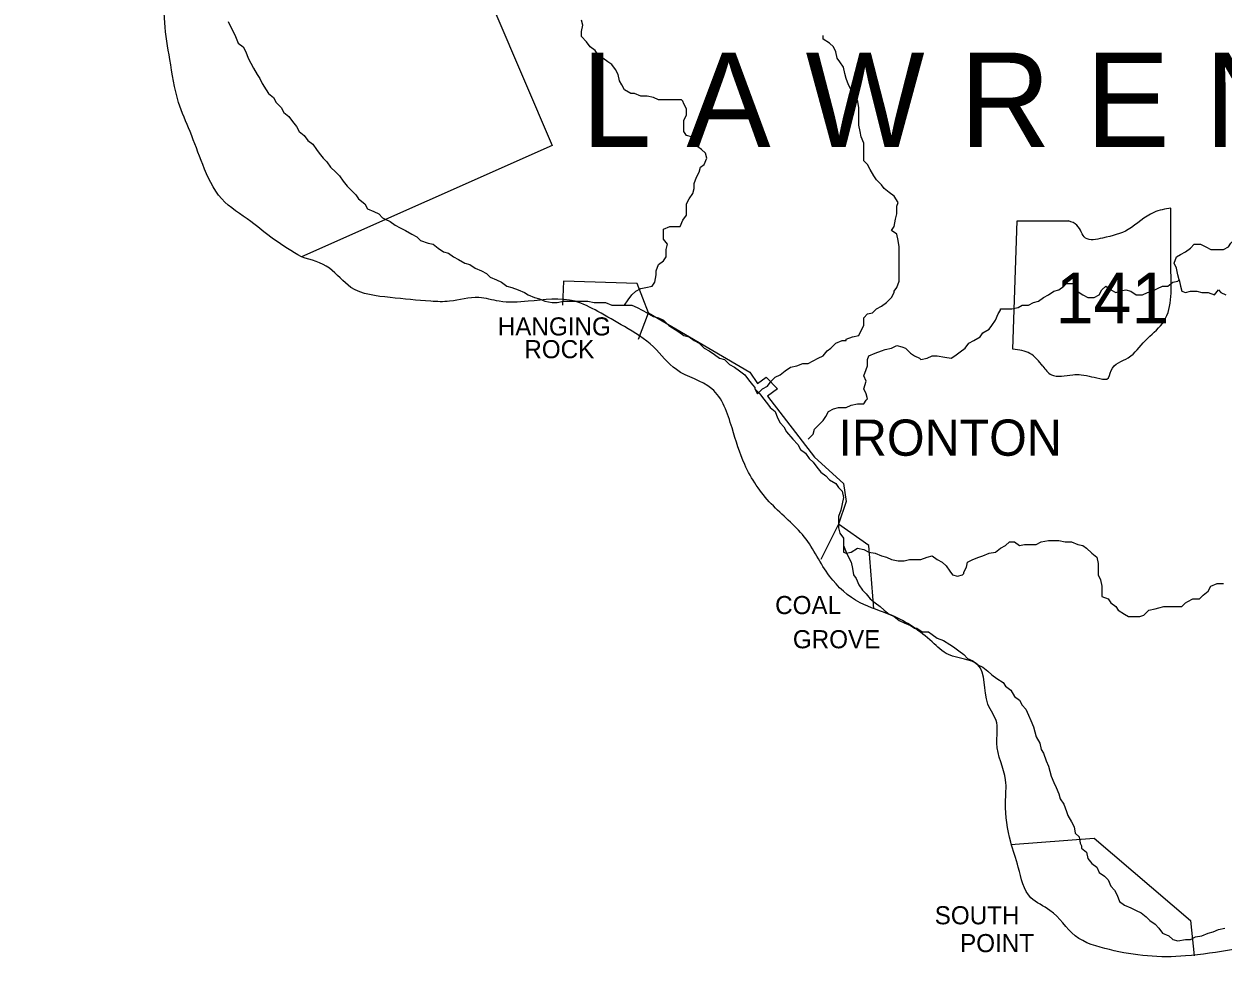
# Model space of a CAD drawing. Extents: x 0 to 40.2, y 0 to 22.
# Drawn here: x 6.366 to 7.657, y 14.906 to 15.911 of the extents above; entities that cross this region are included whole.
import ezdxf

# ---------------------------------------------------------------- set-up
doc = ezdxf.new("R2010")
doc.units = 0
doc.layers.add('Default', color=7, linetype='Continuous')
doc.layers.add('TR_Turning_Path1', color=7, linetype='Continuous')

msp = doc.modelspace()

# ---------------------------------------------------------------- linework, layer by layer
at = {"layer": 'Default'}
for points in [[(6.8528, 16.1563), (6.8419, 15.9968), (6.9346, 15.78), (6.6647, 15.66)], [(6.5856, 15.9136), (6.5883, 15.9082), (6.5911, 15.9027), (6.5938, 15.8973), (6.5965, 15.8904), (6.602, 15.8864), (6.6047, 15.8809), (6.6074, 15.8741), (6.6101, 15.8686), (6.6129, 15.8632), (6.617, 15.8564), (6.6197, 15.8523), (6.6224, 15.8468), (6.6265, 15.84), (6.6292, 15.8359), (6.6347, 15.8318), (6.6374, 15.8264), (6.6429, 15.8209), (6.6456, 15.8155), (6.6511, 15.8114), (6.6551, 15.8059), (6.6592, 15.8005), (6.662, 15.795), (6.6674, 15.7909), (6.6715, 15.7855), (6.677, 15.7814), (6.681, 15.7759), (6.6838, 15.7718), (6.6879, 15.7664), (6.692, 15.7623), (6.696, 15.7568), (6.7015, 15.7514), (6.7056, 15.7473), (6.7097, 15.7418), (6.7138, 15.7364), (6.7179, 15.7323), (6.7233, 15.7268), (6.726, 15.7227), (6.7329, 15.7173), (6.7356, 15.7118), (6.7424, 15.7091), (6.7479, 15.7064), (6.7519, 15.7023), (6.7547, 15.7009)], [(7.0737, 15.8291), (7.0683, 15.8291), (7.0614, 15.8291), (7.0546, 15.8291), (7.0492, 15.8291), (7.0437, 15.8318), (7.0369, 15.8332), (7.0301, 15.8332), (7.0233, 15.8359), (7.0192, 15.8359), (7.0124, 15.84), (7.0096, 15.8454), (7.0069, 15.8495), (7.0055, 15.8564), (7.0028, 15.8618), (6.9987, 15.8673), (6.9946, 15.87), (6.9892, 15.8741), (6.9837, 15.8782), (6.981, 15.8823), (6.9755, 15.8864), (6.9715, 15.8918), (6.966, 15.8973), (6.966, 15.9027), (6.9674, 15.9095), (6.966, 15.915)], [(7.2619, 15.8291), (7.2605, 15.8359), (7.2564, 15.84), (7.2537, 15.8454), (7.251, 15.8523), (7.2496, 15.8577), (7.2482, 15.8645), (7.2441, 15.87), (7.2414, 15.8741), (7.2401, 15.8809), (7.2373, 15.8864), (7.2332, 15.8904), (7.2264, 15.8945), (7.2264, 15.8986)], [(7.0983, 15.7596), (7.101, 15.7664), (7.0996, 15.7718), (7.0955, 15.7759), (7.0914, 15.7786), (7.0873, 15.7827), (7.0846, 15.7895), (7.0792, 15.7909), (7.0764, 15.795), (7.0764, 15.8005), (7.0764, 15.8073), (7.0792, 15.8127), (7.0792, 15.8195), (7.0764, 15.825), (7.0751, 15.8277), (7.0737, 15.8291)], [(7.3069, 15.6777), (7.3055, 15.6846), (7.3, 15.6887), (7.3028, 15.6927), (7.3041, 15.7009), (7.3055, 15.7064), (7.3055, 15.7146), (7.3069, 15.7187), (7.3028, 15.7255), (7.2973, 15.7296), (7.2919, 15.7336), (7.2891, 15.7377), (7.2837, 15.7432), (7.281, 15.7473), (7.2769, 15.7541), (7.2741, 15.7596), (7.27, 15.7636), (7.27, 15.7705), (7.27, 15.7773), (7.27, 15.7827), (7.2673, 15.7895), (7.266, 15.795), (7.2646, 15.8018), (7.2646, 15.8086), (7.2646, 15.8155), (7.2646, 15.8209), (7.2632, 15.8291), (7.2619, 15.8291)], [(7.0574, 15.6614), (7.0574, 15.6682), (7.0587, 15.6737), (7.0546, 15.6791), (7.0546, 15.6846), (7.0546, 15.69), (7.0614, 15.6927), (7.0683, 15.6927), (7.0723, 15.6927), (7.0751, 15.6996), (7.0792, 15.705), (7.0792, 15.7105), (7.0792, 15.7173), (7.0819, 15.7227), (7.086, 15.7282), (7.0873, 15.7336), (7.0873, 15.7391), (7.0901, 15.7459), (7.0928, 15.7514), (7.0942, 15.7568), (7.0983, 15.7596), (7.0983, 15.7596)], [(7.6008, 15.6436), (7.6008, 15.7126)], [(6.7547, 15.7009), (6.7601, 15.6982), (6.7656, 15.6941), (6.771, 15.6914), (6.7765, 15.6887), (6.7833, 15.6846), (6.7888, 15.6818), (6.7928, 15.6777), (6.801, 15.675), (6.8065, 15.6737), (6.8119, 15.6696), (6.8174, 15.6655), (6.8228, 15.6641), (6.8283, 15.66), (6.8338, 15.6573), (6.8406, 15.6532), (6.846, 15.6518), (6.8515, 15.6478), (6.8583, 15.645), (6.8637, 15.6423), (6.8678, 15.6382), (6.8747, 15.6355), (6.8801, 15.6328), (6.8856, 15.6287), (6.891, 15.6273), (6.8978, 15.6246), (6.9046, 15.6218), (6.9087, 15.6191), (6.9156, 15.6164), (6.921, 15.615), (6.9265, 15.6123), (6.9346, 15.6109), (6.9401, 15.6109), (6.9469, 15.6123), (6.9537, 15.6123), (6.9592, 15.6123), (6.966, 15.6123), (6.9728, 15.6123), (6.9796, 15.6109), (6.9865, 15.6109), (6.9919, 15.6109), (6.9987, 15.6082), (7.0055, 15.6082), (7.0069, 15.6082)], [(7.4306, 15.5608), (7.4352, 15.6988), (7.4904, 15.6988)], [(7.6095, 15.6355), (7.6082, 15.6409), (7.6068, 15.6478), (7.6041, 15.6532), (7.6068, 15.66), (7.6109, 15.6628), (7.6164, 15.6655), (7.6218, 15.6696), (7.6259, 15.6737), (7.6327, 15.6737), (7.6382, 15.6709), (7.6436, 15.6682), (7.6504, 15.6682), (7.6573, 15.6682), (7.6627, 15.6709), (7.6654, 15.675), (7.6709, 15.6805), (7.675, 15.6846), (7.6818, 15.6887), (7.6818, 15.6887), (7.6832, 15.69)], [(7.3028, 15.6232), (7.3055, 15.6273), (7.3082, 15.6341), (7.3082, 15.6409), (7.3082, 15.6464), (7.3082, 15.6518), (7.3082, 15.66), (7.3082, 15.6655), (7.3082, 15.6709), (7.3069, 15.6777), (7.3069, 15.6777)], [(7.3028, 15.6232), (7.3055, 15.6273), (7.3082, 15.6341), (7.3082, 15.6409), (7.3082, 15.6464), (7.3082, 15.6518), (7.3082, 15.66), (7.3082, 15.6655), (7.3082, 15.6709), (7.3069, 15.6777), (7.3069, 15.6777)], [(7.0069, 15.6082), (7.0124, 15.6082), (7.0164, 15.6137), (7.0205, 15.6191), (7.0246, 15.6232), (7.0301, 15.6259), (7.0355, 15.6273), (7.0424, 15.6287), (7.0451, 15.6328), (7.0464, 15.6409), (7.0464, 15.645), (7.0492, 15.6518), (7.0546, 15.6559), (7.0574, 15.66), (7.0574, 15.6614)], [(7.0274, 15.5714), (7.0383, 15.6), (7.026, 15.6314), (6.9469, 15.6341), (6.9456, 15.6082)], [(7.5114, 15.6164), (7.5182, 15.6164), (7.5236, 15.6191), (7.5264, 15.6246), (7.5305, 15.6287), (7.5359, 15.6246), (7.5414, 15.6218), (7.5455, 15.6232), (7.5523, 15.6246), (7.5577, 15.6232), (7.5632, 15.6191), (7.57, 15.6191), (7.5755, 15.6218), (7.5809, 15.6232), (7.5864, 15.6259), (7.5918, 15.6287), (7.5973, 15.6287), (7.6027, 15.6328), (7.6082, 15.6341), (7.6095, 15.6355)], [(7.6095, 15.6355), (7.6109, 15.6287), (7.6123, 15.6232), (7.6164, 15.6218), (7.6218, 15.6232), (7.6286, 15.6232), (7.6341, 15.6218), (7.6409, 15.6218), (7.6477, 15.6191), (7.6518, 15.6246), (7.6545, 15.6218), (7.66, 15.6191)], [(7.251, 15.5714), (7.2578, 15.5741), (7.2646, 15.5755), (7.2673, 15.5809), (7.27, 15.5864), (7.27, 15.5946), (7.2741, 15.5987), (7.2796, 15.6), (7.2837, 15.6041), (7.2891, 15.6069), (7.2946, 15.6109), (7.3, 15.6164), (7.3028, 15.6218), (7.3028, 15.6232)], [(7.251, 15.5714), (7.2578, 15.5741), (7.2646, 15.5755), (7.2673, 15.5809), (7.27, 15.5864), (7.27, 15.5946), (7.2741, 15.5987), (7.2796, 15.6), (7.2837, 15.6041), (7.2891, 15.6069), (7.2946, 15.6109), (7.3, 15.6164), (7.3028, 15.6218), (7.3028, 15.6232)], [(7.4173, 15.6041), (7.4227, 15.6041), (7.4296, 15.6041), (7.4364, 15.6055), (7.4405, 15.6082), (7.4473, 15.6082), (7.4527, 15.6109), (7.4582, 15.6123), (7.4637, 15.6164), (7.4691, 15.6191), (7.4746, 15.6232), (7.48, 15.6246), (7.4855, 15.6287), (7.4882, 15.6314), (7.495, 15.6314), (7.4964, 15.6259), (7.5018, 15.6218), (7.5059, 15.6191), (7.5114, 15.6164), (7.5114, 15.6164), (7.5114, 15.6164)], [(7.0069, 15.6082), (7.0137, 15.6082), (7.0205, 15.6082), (7.026, 15.6055), (7.0314, 15.6028), (7.0369, 15.6), (7.0437, 15.5959), (7.0492, 15.5946), (7.0546, 15.5919), (7.0601, 15.5864), (7.0642, 15.5837), (7.071, 15.5796), (7.0764, 15.5755), (7.0819, 15.5741), (7.0873, 15.57), (7.0928, 15.5673), (7.0983, 15.5619), (7.1037, 15.5591), (7.1092, 15.555), (7.1146, 15.551), (7.1201, 15.5496), (7.1255, 15.5441), (7.131, 15.5414), (7.1364, 15.5373), (7.1419, 15.5332), (7.146, 15.5278), (7.1501, 15.5223), (7.1528, 15.5196), (7.1528, 15.5196), (7.1528, 15.5182)], [(7.0383, 15.6), (7.1473, 15.536), (7.1555, 15.5237), (7.1651, 15.5305), (7.1773, 15.5182), (7.1664, 15.51), (7.2169, 15.4446), (7.2482, 15.416), (7.251, 15.3969), (7.2428, 15.3723)], [(7.3314, 15.5496), (7.3382, 15.551), (7.3437, 15.5537), (7.3491, 15.5537), (7.3573, 15.5523), (7.3641, 15.551), (7.3682, 15.5537), (7.3737, 15.5578), (7.3791, 15.5619), (7.3832, 15.5673), (7.3887, 15.57), (7.3955, 15.5741), (7.3982, 15.5782), (7.405, 15.5823), (7.4078, 15.5864), (7.4118, 15.5919), (7.4146, 15.5987), (7.4173, 15.6028), (7.4173, 15.6041)], [(7.1528, 15.5182), (7.1555, 15.5128), (7.161, 15.5182), (7.1664, 15.521), (7.1705, 15.5264), (7.1746, 15.5305), (7.1801, 15.5332), (7.1855, 15.5373), (7.191, 15.5414), (7.1978, 15.5428), (7.2046, 15.5455), (7.2101, 15.5455), (7.2155, 15.5482), (7.221, 15.551), (7.2264, 15.5537), (7.2305, 15.5591), (7.2346, 15.5619), (7.2401, 15.5673), (7.2469, 15.57), (7.251, 15.57), (7.251, 15.5714)], [(7.1528, 15.5182), (7.1555, 15.5128), (7.161, 15.5182), (7.1664, 15.521), (7.1705, 15.5264), (7.1746, 15.5305), (7.1801, 15.5332), (7.1855, 15.5373), (7.191, 15.5414), (7.1978, 15.5428), (7.2046, 15.5455), (7.2101, 15.5455), (7.2155, 15.5482), (7.221, 15.551), (7.2264, 15.5537), (7.2305, 15.5591), (7.2346, 15.5619), (7.2401, 15.5673), (7.2469, 15.57), (7.251, 15.57), (7.251, 15.5714)], [(7.2741, 15.5073), (7.2728, 15.5128), (7.27, 15.5182), (7.2728, 15.5264), (7.27, 15.5319), (7.2728, 15.5387), (7.2741, 15.5428), (7.2741, 15.5496), (7.2755, 15.5537), (7.2823, 15.5564), (7.2891, 15.5591), (7.2932, 15.5605), (7.3, 15.5619), (7.3055, 15.5646), (7.3109, 15.5632), (7.315, 15.5619), (7.3205, 15.5564), (7.3246, 15.5537), (7.33, 15.551), (7.3314, 15.5496), (7.3314, 15.5496)], [(7.1528, 15.5182), (7.1582, 15.5128), (7.161, 15.5087), (7.1664, 15.5019), (7.1692, 15.4978), (7.1746, 15.4937), (7.1773, 15.4869), (7.1801, 15.4814), (7.1841, 15.4773), (7.1869, 15.4719), (7.1937, 15.4637), (7.1937, 15.4637)], [(7.2101, 15.4637), (7.2155, 15.4691), (7.2169, 15.4746), (7.221, 15.4787), (7.2264, 15.4841), (7.2291, 15.4882), (7.2319, 15.4937), (7.2373, 15.4964), (7.2428, 15.4978), (7.251, 15.4978), (7.2564, 15.5005), (7.2632, 15.5019), (7.27, 15.5019), (7.2728, 15.506), (7.2741, 15.5073)], [(7.1937, 15.4637), (7.1991, 15.4582), (7.2019, 15.4528), (7.2073, 15.4487), (7.2114, 15.4432), (7.2155, 15.4391), (7.2196, 15.4337), (7.2237, 15.4282), (7.2291, 15.4242), (7.2332, 15.4201), (7.2401, 15.416), (7.2428, 15.4119), (7.2469, 15.4078), (7.2482, 15.401), (7.2469, 15.3942), (7.2455, 15.3873), (7.2428, 15.3805), (7.2428, 15.3751), (7.2428, 15.3683), (7.2441, 15.3628), (7.2482, 15.3573), (7.2482, 15.3492), (7.2482, 15.3492)], [(7.281, 15.281), (7.2755, 15.3492), (7.2428, 15.3723), (7.2237, 15.3342)], [(7.2482, 15.3492), (7.251, 15.3423), (7.2537, 15.3369), (7.2564, 15.3314), (7.2578, 15.3246), (7.2591, 15.3178), (7.2619, 15.3137), (7.2646, 15.3069), (7.2687, 15.3014), (7.2728, 15.2974), (7.2769, 15.2919), (7.2823, 15.2878), (7.2878, 15.2837), (7.2919, 15.2796), (7.2973, 15.2755), (7.3028, 15.2728), (7.3082, 15.2687), (7.3137, 15.266), (7.3205, 15.2633), (7.3246, 15.2605), (7.3273, 15.2605)], [(7.2482, 15.3492), (7.2482, 15.3423), (7.251, 15.341), (7.2564, 15.3423), (7.2632, 15.3464), (7.27, 15.3451), (7.2755, 15.3423), (7.2823, 15.341), (7.2891, 15.3383), (7.2946, 15.3369), (7.3, 15.3342), (7.3069, 15.3328), (7.3137, 15.3328), (7.3191, 15.3342), (7.3246, 15.3342), (7.3314, 15.3342), (7.3382, 15.3369), (7.3437, 15.3383), (7.3491, 15.3342), (7.3546, 15.3314), (7.3587, 15.3273), (7.3628, 15.3219), (7.3655, 15.3178), (7.3709, 15.3164), (7.3764, 15.3178), (7.3778, 15.3192), (7.3778, 15.3205)], [(7.3778, 15.3205), (7.3805, 15.326), (7.3818, 15.3314), (7.3873, 15.3342), (7.3941, 15.3369), (7.3982, 15.3383), (7.405, 15.341), (7.4118, 15.3423), (7.4173, 15.3464), (7.4227, 15.3492), (7.4268, 15.3533), (7.4323, 15.3533), (7.4377, 15.3492), (7.4432, 15.3505), (7.45, 15.3505), (7.4555, 15.3505), (7.4609, 15.3533), (7.4691, 15.3546), (7.4746, 15.3546), (7.48, 15.3546), (7.4868, 15.3533), (7.4936, 15.3533), (7.5005, 15.3505), (7.5059, 15.3492), (7.51, 15.3464), (7.5155, 15.341), (7.5209, 15.3369), (7.5209, 15.3369), (7.5209, 15.3369)], [(7.5209, 15.3369), (7.5223, 15.3301), (7.5223, 15.3246), (7.5223, 15.3178), (7.525, 15.3124), (7.5264, 15.3055), (7.5264, 15.3001), (7.5264, 15.2946), (7.5332, 15.2919), (7.5359, 15.2878), (7.5414, 15.2837), (7.5441, 15.2796), (7.5509, 15.2755), (7.555, 15.2728), (7.5618, 15.2728), (7.5673, 15.2728), (7.5714, 15.2742), (7.5714, 15.2742)], [(7.6191, 15.2892), (7.6245, 15.2919), (7.6314, 15.2919), (7.6354, 15.296), (7.6409, 15.3001), (7.6436, 15.3055), (7.6504, 15.3083), (7.6573, 15.3083)], [(7.5714, 15.2742), (7.5768, 15.2796), (7.5836, 15.281), (7.5877, 15.2824), (7.5932, 15.2837), (7.6, 15.2837), (7.6068, 15.2837), (7.6123, 15.2837), (7.6164, 15.2878), (7.6191, 15.2892)], [(7.3273, 15.2605), (7.3328, 15.2565), (7.3396, 15.2565), (7.3437, 15.2537), (7.3491, 15.2496), (7.3559, 15.2469), (7.3628, 15.2428), (7.3668, 15.2401), (7.3723, 15.236), (7.3778, 15.2319), (7.3818, 15.2278), (7.3873, 15.2251), (7.3928, 15.221), (7.3982, 15.2183), (7.4037, 15.2142), (7.4078, 15.2101), (7.4132, 15.206), (7.42, 15.2019), (7.4227, 15.1978), (7.4282, 15.1937), (7.4323, 15.1869), (7.4377, 15.1828), (7.4405, 15.1774), (7.4446, 15.1733), (7.4473, 15.1665), (7.45, 15.161), (7.4527, 15.1542), (7.4541, 15.1487), (7.4555, 15.1433), (7.4596, 15.1365), (7.4609, 15.1297), (7.4637, 15.1256), (7.4664, 15.1174), (7.4691, 15.1119), (7.4705, 15.1065), (7.4718, 15.101), (7.4746, 15.0942), (7.4773, 15.0888), (7.48, 15.0819), (7.4814, 15.0765), (7.4855, 15.071), (7.4882, 15.0628), (7.4896, 15.0588), (7.4936, 15.0519), (7.4964, 15.0465), (7.4977, 15.0397), (7.5018, 15.0356), (7.5032, 15.0288), (7.5046, 15.026), (7.5046, 15.0233)], [(7.4282, 15.0274), (7.5182, 15.0342), (7.6218, 14.9456), (7.6259, 14.9074)], [(7.5046, 15.0233), (7.51, 15.0192), (7.5114, 15.0124), (7.5155, 15.0069), (7.5209, 15.0029), (7.5236, 14.9974), (7.5291, 14.9933), (7.5332, 14.9892), (7.5359, 14.9824), (7.54, 14.9783), (7.5427, 14.9729), (7.5455, 14.966), (7.5509, 14.962), (7.5577, 14.9592), (7.5632, 14.9565), (7.5686, 14.9538), (7.5741, 14.9497), (7.5782, 14.9456), (7.5836, 14.9415), (7.5877, 14.9374), (7.5877, 14.9374), (7.5877, 14.9374)], [(7.5877, 14.9374), (7.5918, 14.932), (7.5986, 14.9292), (7.6027, 14.9251), (7.6082, 14.9238), (7.6164, 14.9251), (7.6218, 14.9251), (7.6273, 14.9279), (7.6341, 14.9292), (7.6409, 14.932), (7.6463, 14.9333), (7.6518, 14.936), (7.6586, 14.9374)]]:
    msp.add_lwpolyline(points, dxfattribs=at)
for points in [[(6.6647, 15.66), (6.6347, 15.6791), (6.6101, 15.6982), (6.5788, 15.7227), (6.5583, 15.7596), (6.5447, 15.795), (6.5324, 15.8264), (6.5229, 15.8727), (6.5174, 15.9123), (6.5174, 15.9545), (6.5174, 15.9927), (6.5147, 16.0445), (6.5011, 16.0854), (6.4902, 16.1195), (6.4738, 16.1454), (6.4574, 16.1645), (6.4493, 16.1918), (6.4493, 16.234), (6.4629, 16.2695), (6.4724, 16.3117), (6.4724, 16.3554), (6.4656, 16.3976), (6.4629, 16.4385), (6.4465, 16.4685), (6.4288, 16.4849), (6.4015, 16.4999), (6.3852, 16.5026), (6.3593, 16.4944), (6.3456, 16.4917), (6.3102, 16.4822), (6.2734, 16.474), (6.2393, 16.4576), (6.212, 16.4385), (6.1861, 16.4222), (6.1548, 16.4045), (6.1289, 16.3895), (6.1098, 16.3785), (6.0866, 16.3704), (6.0511, 16.3717), (6.0171, 16.3785), (5.983, 16.3813), (5.9448, 16.3881), (5.9189, 16.3704), (5.8957, 16.3526), (5.8766, 16.3117), (5.8589, 16.2872), (5.8357, 16.2517), (5.8166, 16.2177), (5.7935, 16.2081), (5.7539, 16.1918), (5.7212, 16.1754), (5.6803, 16.1631), (5.653, 16.1481), (5.6162, 16.1318), (5.5944, 16.1018), (5.5821, 16.0772), (5.5685, 16.0418), (5.559, 16.0077), (5.5562, 15.9668), (5.5249, 15.9382), (5.4908, 15.9123), (5.4431, 15.8891), (5.3926, 15.8891), (5.3517, 15.8809), (5.3067, 15.8809), (5.2631, 15.8864), (5.2222, 15.9054), (5.1963, 15.9232), (5.1622, 15.93), (5.1363, 15.9313), (5.1186, 15.915), (5.0845, 15.9041), (5.0613, 15.8864)], [(8.5448, 15.7159), (8.5244, 15.69), (8.5176, 15.6655), (8.5244, 15.6273), (8.5176, 15.6123), (8.5148, 15.585), (8.508, 15.5591), (8.508, 15.5387), (8.508, 15.51), (8.5026, 15.4882), (8.493, 15.4691), (8.4835, 15.4432), (8.4835, 15.4119), (8.4835, 15.3737), (8.4835, 15.3369), (8.4726, 15.3096), (8.4617, 15.2742), (8.4535, 15.236), (8.4508, 15.2101), (8.444, 15.1828), (8.429, 15.146), (8.4126, 15.1092), (8.3976, 15.0942), (8.3662, 15.0765), (8.3349, 15.0724), (8.2953, 15.0628), (8.2599, 15.0628), (8.2299, 15.0547), (8.1999, 15.0519), (8.1754, 15.0451), (8.1549, 15.0451), (8.1331, 15.0547), (8.1126, 15.0656), (8.0854, 15.0547), (8.0622, 15.0451), (8.0417, 15.0356), (8.0158, 15.0288), (7.9777, 15.0206), (7.9436, 15.0097), (7.9136, 15.0029), (7.8836, 14.9919), (7.8522, 14.9783), (7.8195, 14.966), (7.7881, 14.9565), (7.7527, 14.9374), (7.72, 14.9238), (7.6682, 14.9142), (7.6164, 14.9074), (7.5755, 14.9074), (7.5345, 14.9142), (7.4977, 14.9292), (7.4705, 14.9565), (7.45, 14.9701), (7.4364, 15.0029), (7.4282, 15.0301), (7.4227, 15.0724), (7.4227, 15.0969), (7.4132, 15.1365), (7.4132, 15.1583), (7.4037, 15.1787), (7.3928, 15.221), (7.3614, 15.2319), (7.3437, 15.2455), (7.3, 15.2742), (7.266, 15.2878), (7.2332, 15.3164), (7.206, 15.3587), (7.1705, 15.3942), (7.1419, 15.4364), (7.1282, 15.476), (7.1064, 15.5182), (7.0683, 15.5387), (7.0437, 15.5632), (7.0124, 15.585), (6.9837, 15.6014), (6.9592, 15.6123), (6.9087, 15.6123), (6.8774, 15.6123), (6.8556, 15.6164), (6.8242, 15.6123), (6.8038, 15.6123), (6.7601, 15.6164), (6.7179, 15.6273), (6.6947, 15.6478), (6.6647, 15.66)], [(7.6008, 15.7126), (7.5824, 15.708), (7.5548, 15.6896), (7.5272, 15.6804), (7.5088, 15.6804), (7.4996, 15.6942), (7.4904, 15.6988)], [(7.4628, 15.5424), (7.472, 15.5332), (7.495, 15.5332), (7.5042, 15.5332), (7.5272, 15.5286), (7.5318, 15.5286), (7.5364, 15.5378), (7.5548, 15.5516), (7.5732, 15.57), (7.5916, 15.5884), (7.6008, 15.6436)], [(7.4628, 15.5424), (7.449, 15.5562), (7.4306, 15.5608)]]:
    msp.add_spline(points, degree=3, dxfattribs=at)

# ---------------------------------------------------------------- texts
for s, height, p in [('141', 0.05486, (7.4766, 15.5884)), ('HANGING', 0.0195, (6.876, 15.5755)), ('ROCK', 0.0195, (6.9046, 15.551)), ('IRONTON', 0.039, (7.2428, 15.446)), ('COAL', 0.0195, (7.1746, 15.2755)), ('GROVE', 0.0195, (7.1937, 15.2387)), ('SOUTH', 0.0195, (7.3464, 14.9415)), ('POINT', 0.0195, (7.3737, 14.9115))]:
    msp.add_text(s, height=height, dxfattribs=at).set_placement(p)
at = {"layer": 'TR_Turning_Path1'}
msp.add_text('L A W R E N C E', height=0.101489, dxfattribs=at).set_placement((6.966, 15.7786))

doc.saveas('drawing.dxf')
